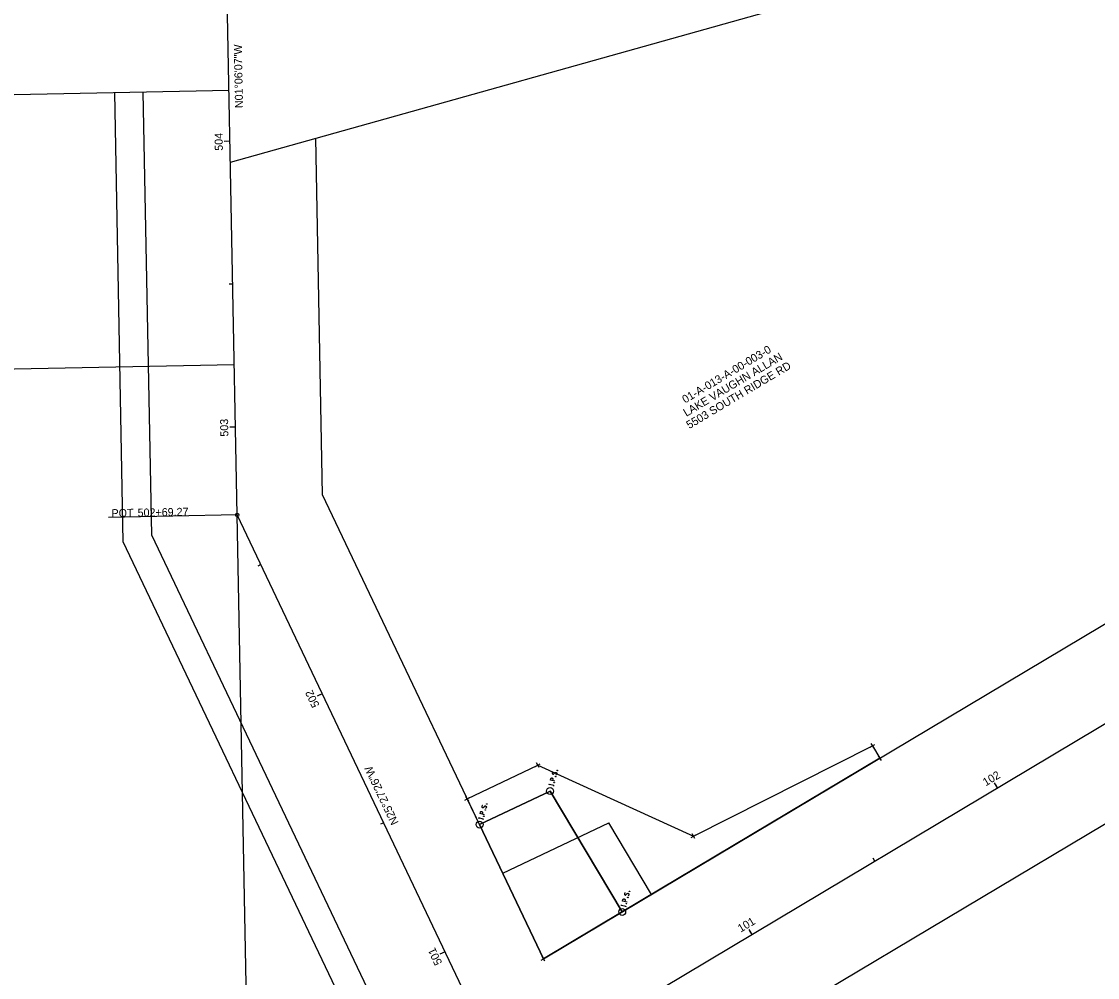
# Model space of a CAD drawing. Extents: x 2351593 to 2354159, y 766293 to 768001.
# Drawn here: x 2352246.2 to 2352622.6, y 766967.1 to 767301.5 of the extents above; entities that cross this region are included whole.
import ezdxf

# ---------------------------------------------------------------- set-up
doc = ezdxf.new("R2010")
doc.units = 0
for name, color, linetype in [('DV_X_Property_Line', 7, 'Continuous'), ('DV_X_Section_VMS_Line', 7, 'Continuous'), ('PTS_ANNO', 7, 'Continuous'), ('RW_P_Easement_Area', 7, 'Continuous'), ('RW_P_Esmt_SH', 7, 'Continuous'), ('RW_P_Esmt_TMP', 7, 'Continuous'), ('RW_P_Taking_Area', 7, 'Continuous'), ('RW_X_CL_100_Bearings', 7, 'Continuous'), ('RW_X_CL_100_Cardinal_Points', 7, 'Continuous'), ('RW_X_CL_500_Bearings', 7, 'Continuous'), ('RW_X_CL_500_Cardinal_Points', 7, 'Continuous'), ('RW_X_CL_500_Stations', 7, 'Continuous'), ('RW_X_Esmt_U', 7, 'Continuous'), ('SC_Scratch1', 7, 'Continuous'), ('SC_Scratch2', 7, 'Continuous'), ('SC_Scratch3', 7, 'Continuous'), ('SC_Scratch4', 7, 'Continuous'), ('SV_P_Control_Cells_Set', 7, 'Continuous'), ('SV_P_Mon_Cells_Set', 7, 'Continuous'), ('V-SURV-PARL-LINE', 7, 'Continuous'), ('V-SURV-RWAY-CNTR', 7, 'Continuous')]:
    doc.layers.add(name, color=color, linetype=linetype)

msp = doc.modelspace()

# ---------------------------------------------------------------- linework, layer by layer
at = {"layer": 'DV_X_Property_Line'}
for p, q in [((2352319.24, 767252.27), (2352591.72, 767328.7)), ((2352318.76, 767277.31), (2352107.01, 767273.24)), ((2352320.6, 767181.33), (2352109.81, 767177.28))]:
    msp.add_line(p, q, dxfattribs=at)
at = {"layer": 'DV_X_Section_VMS_Line'}
msp.add_line((2352337.69, 766292.88), (2352321.61, 767128.88), dxfattribs=at)
at = {"layer": 'PTS_ANNO'}
for p, q in [((2352428.78, 766973.55), (2354128.21, 767987.61)), ((2352450.22, 766916.47), (2354158.95, 767936.09)), ((2352291.74, 767121.83), (2352288.76, 767276.74)), ((2352351.48, 767135.93), (2352349.08, 767260.64)), ((2352428.78, 766973.55), (2352351.48, 767135.93)), ((2352377.03, 766942.67), (2352291.74, 767121.83))]:
    msp.add_line(p, q, dxfattribs=at)
at = {"layer": 'RW_P_Easement_Area'}
for p, q in [((2352481.24, 767016.49), (2352543.91, 767048.07)), ((2352543.91, 767048.07), (2352546.47, 767043.77)), ((2352546.47, 767043.77), (2352456.31, 766989.97)), ((2352402.11, 767029.58), (2352426.77, 767041.31)), ((2352426.77, 767041.31), (2352481.24, 767016.49)), ((2352431.06, 767032.28), (2352406.41, 767020.54)), ((2352456.31, 766989.97), (2352431.06, 767032.28)), ((2352406.41, 767020.54), (2352402.11, 767029.58))]:
    msp.add_line(p, q, dxfattribs=at)
at = {"layer": 'RW_P_Esmt_SH'}
for p, q in [((2352406.41, 767020.54), (2352431.06, 767032.28)), ((2352406.41, 767020.54), (2352431.06, 767032.28)), ((2352431.06, 767032.28), (2352456.31, 766989.97)), ((2352431.06, 767032.28), (2352456.31, 766989.97))]:
    msp.add_line(p, q, dxfattribs=at)
at = {"layer": 'RW_P_Esmt_TMP'}
for p, q in [((2352481.24, 767016.49), (2352543.91, 767048.07)), ((2352543.91, 767048.07), (2352546.47, 767043.77)), ((2352402.11, 767029.57), (2352426.76, 767041.31)), ((2352426.76, 767041.31), (2352481.24, 767016.49))]:
    msp.add_line(p, q, dxfattribs=at)
at = {"layer": 'RW_P_Taking_Area'}
for p, q in [((2352406.41, 767020.54), (2352431.06, 767032.28)), ((2352431.06, 767032.28), (2352456.31, 766989.97)), ((2352428.78, 766973.55), (2352406.41, 767020.54)), ((2352456.31, 766989.97), (2352428.78, 766973.55))]:
    msp.add_line(p, q, dxfattribs=at)
at = {"layer": 'RW_X_CL_100_Cardinal_Points'}
msp.add_line((2352321.61, 767128.88), (2352276.62, 767128.01), dxfattribs=at)
msp.add_circle((2352321.61, 767128.88), 0.6, dxfattribs=at)
at = {"layer": 'RW_X_CL_500_Cardinal_Points'}
msp.add_line((2352321.61, 767128.88), (2352276.62, 767128.01), dxfattribs=at)
msp.add_circle((2352321.61, 767128.88), 0.6, dxfattribs=at)
at = {"layer": 'RW_X_CL_500_Stations'}
for p, q in [((2352319.1, 767259.59), (2352317.9, 767259.56)), ((2352321.02, 767159.6), (2352319.82, 767159.58)), ((2352351.38, 767066.34), (2352350.3, 767065.82)), ((2352587.61, 767033.38), (2352586.99, 767034.41)), ((2352501.73, 766982.14), (2352501.12, 766983.17)), ((2352394.37, 766976.05), (2352393.28, 766975.53))]:
    msp.add_line(p, q, dxfattribs=at)
at = {"layer": 'RW_X_Esmt_U'}
for p, q in [((2352281.78, 767119.48), (2352278.76, 767276.54)), ((2352368.41, 766937.52), (2352281.78, 767119.48))]:
    msp.add_line(p, q, dxfattribs=at)
at = {"layer": 'SC_Scratch2'}
msp.add_lwpolyline([(2352431.06, 767032.28), (2352406.41, 767020.54), (2352428.78, 766973.55), (2352456.31, 766989.97)], close=True, dxfattribs=at)
at = {"layer": 'SC_Scratch3'}
msp.add_lwpolyline([(2352402.11, 767029.57), (2352426.76, 767041.31), (2352481.24, 767016.49), (2352543.91, 767048.07), (2352546.47, 767043.77), (2352456.31, 766989.97), (2352431.06, 767032.28), (2352406.41, 767020.54)], close=True, dxfattribs=at)
at = {"layer": 'SC_Scratch4'}
for p in [(2352414.52, 767003.5), (2352466.61, 766996.12)]:
    msp.add_line(p, (2352451.66, 767021.18), dxfattribs=at)
at = {"layer": 'SV_P_Control_Cells_Set'}
for p, q in [((2352543.1, 767047.58), (2352544.72, 767048.55)), ((2352544.39, 767047.26), (2352543.43, 767048.88)), ((2352545.66, 767043.29), (2352547.28, 767044.26)), ((2352546.96, 767042.96), (2352545.99, 767044.58)), ((2352425.96, 767040.82), (2352427.58, 767041.79)), ((2352427.25, 767040.5), (2352426.28, 767042.12)), ((2352401.3, 767029.09), (2352402.93, 767030.06)), ((2352402.6, 767028.77), (2352401.63, 767030.39)), ((2352481.72, 767015.68), (2352480.75, 767017.3)), ((2352480.43, 767016.01), (2352482.05, 767016.97)), ((2352427.97, 766973.06), (2352429.59, 766974.03)), ((2352429.27, 766972.74), (2352428.3, 766974.36))]:
    msp.add_line(p, q, dxfattribs=at)
at = {"layer": 'SV_P_Mon_Cells_Set'}
for points in [[(2352432.75, 767035.73), (2352431.2, 767036.12), (2352431.33, 767036.63), (2352431.36, 767036.68), (2352431.4, 767036.75), (2352431.43, 767036.78), (2352431.47, 767036.81), (2352431.54, 767036.83), (2352431.61, 767036.85), (2352431.71, 767036.85), (2352431.86, 767036.81), (2352431.9, 767036.79), (2352431.97, 767036.75), (2352432.05, 767036.68), (2352432.07, 767036.63), (2352432.09, 767036.59), (2352432.1, 767036.53), (2352432.09, 767036.44), (2352431.96, 767035.93)], [(2352432.05, 767039.01), (2352432.02, 767039), (2352431.99, 767038.97), (2352431.93, 767038.88), (2352431.87, 767038.77), (2352431.85, 767038.69), (2352431.84, 767038.65), (2352431.84, 767038.51), (2352431.89, 767038.37), (2352431.97, 767038.27), (2352432.06, 767038.22), (2352432.13, 767038.21), (2352432.23, 767038.2), (2352432.34, 767038.27), (2352432.86, 767038.76), (2352432.92, 767038.8), (2352432.97, 767038.81), (2352433.05, 767038.81), (2352433.13, 767038.8), (2352433.2, 767038.77), (2352433.24, 767038.74), (2352433.3, 767038.71), (2352433.34, 767038.67), (2352433.37, 767038.64), (2352433.4, 767038.6), (2352433.42, 767038.56), (2352433.43, 767038.51), (2352433.43, 767038.48), (2352433.42, 767038.38), (2352433.38, 767038.23), (2352433.34, 767038.14), (2352433.22, 767038.02), (2352433.12, 767037.96)], [(2352432.95, 767037.37), (2352432.96, 767037.43), (2352432.99, 767037.45), (2352433.05, 767037.47), (2352433.11, 767037.46), (2352433.15, 767037.41), (2352433.17, 767037.38), (2352433.16, 767037.32), (2352433.12, 767037.3), (2352433.07, 767037.28), (2352433, 767037.29), (2352432.96, 767037.34), (2352432.95, 767037.37)], [(2352433.48, 767039.49), (2352433.5, 767039.54), (2352433.53, 767039.57), (2352433.59, 767039.59), (2352433.65, 767039.57), (2352433.69, 767039.53), (2352433.7, 767039.49), (2352433.69, 767039.44), (2352433.66, 767039.41), (2352433.6, 767039.39), (2352433.54, 767039.41), (2352433.5, 767039.45), (2352433.48, 767039.49)], [(2352430.78, 767034.43), (2352430.86, 767034.77)], [(2352432.37, 767034.21), (2352430.82, 767034.6)], [(2352432.33, 767034.04), (2352432.41, 767034.38)], [(2352432.4, 767035.19), (2352432.41, 767035.25), (2352432.44, 767035.27), (2352432.5, 767035.29), (2352432.56, 767035.28), (2352432.6, 767035.23), (2352432.62, 767035.2), (2352432.6, 767035.14), (2352432.57, 767035.12), (2352432.52, 767035.1), (2352432.45, 767035.11), (2352432.41, 767035.16), (2352432.4, 767035.19)], [(2352408.11, 767023.99), (2352406.56, 767024.38), (2352406.68, 767024.9), (2352406.71, 767024.95), (2352406.75, 767025.02), (2352406.79, 767025.04), (2352406.82, 767025.07), (2352406.89, 767025.09), (2352406.96, 767025.11), (2352407.06, 767025.11), (2352407.21, 767025.07), (2352407.26, 767025.05), (2352407.32, 767025.01), (2352407.4, 767024.94), (2352407.42, 767024.89), (2352407.44, 767024.85), (2352407.45, 767024.79), (2352407.44, 767024.71), (2352407.31, 767024.19)], [(2352407.4, 767027.27), (2352407.37, 767027.26), (2352407.34, 767027.23), (2352407.28, 767027.15), (2352407.22, 767027.03), (2352407.2, 767026.95), (2352407.19, 767026.92), (2352407.2, 767026.77), (2352407.24, 767026.63), (2352407.32, 767026.53), (2352407.41, 767026.49), (2352407.48, 767026.47), (2352407.59, 767026.47), (2352407.69, 767026.53), (2352408.21, 767027.02), (2352408.27, 767027.07), (2352408.33, 767027.07), (2352408.4, 767027.08), (2352408.48, 767027.06), (2352408.55, 767027.03), (2352408.59, 767027.01), (2352408.65, 767026.97), (2352408.69, 767026.94), (2352408.73, 767026.91), (2352408.75, 767026.86), (2352408.77, 767026.83), (2352408.78, 767026.78), (2352408.79, 767026.74), (2352408.78, 767026.64), (2352408.74, 767026.49), (2352408.69, 767026.4), (2352408.57, 767026.29), (2352408.47, 767026.22)], [(2352408.3, 767025.64), (2352408.31, 767025.69), (2352408.35, 767025.72), (2352408.4, 767025.74), (2352408.47, 767025.72), (2352408.51, 767025.68), (2352408.52, 767025.64), (2352408.51, 767025.58), (2352408.48, 767025.56), (2352408.42, 767025.54), (2352408.36, 767025.55), (2352408.32, 767025.6), (2352408.3, 767025.64)], [(2352408.84, 767027.75), (2352408.85, 767027.81), (2352408.88, 767027.83), (2352408.94, 767027.85), (2352409, 767027.84), (2352409.04, 767027.79), (2352409.06, 767027.75), (2352409.04, 767027.7), (2352409.01, 767027.67), (2352408.95, 767027.66), (2352408.89, 767027.67), (2352408.85, 767027.71), (2352408.84, 767027.75)], [(2352406.13, 767022.7), (2352406.22, 767023.04)], [(2352407.72, 767022.47), (2352406.17, 767022.87)], [(2352407.68, 767022.3), (2352407.77, 767022.65)], [(2352407.75, 767023.46), (2352407.76, 767023.51), (2352407.8, 767023.54), (2352407.85, 767023.56), (2352407.91, 767023.54), (2352407.96, 767023.5), (2352407.97, 767023.46), (2352407.96, 767023.4), (2352407.93, 767023.38), (2352407.87, 767023.36), (2352407.81, 767023.37), (2352407.77, 767023.42), (2352407.75, 767023.46)], [(2352458, 766993.42), (2352456.45, 766993.81), (2352456.58, 766994.32), (2352456.6, 766994.37), (2352456.65, 766994.44), (2352456.68, 766994.47), (2352456.71, 766994.5), (2352456.78, 766994.52), (2352456.85, 766994.54), (2352456.96, 766994.54), (2352457.1, 766994.5), (2352457.15, 766994.48), (2352457.22, 766994.44), (2352457.29, 766994.37), (2352457.32, 766994.32), (2352457.33, 766994.28), (2352457.35, 766994.22), (2352457.34, 766994.13), (2352457.21, 766993.62)], [(2352457.3, 766996.7), (2352457.27, 766996.69), (2352457.23, 766996.66), (2352457.17, 766996.57), (2352457.12, 766996.46), (2352457.1, 766996.38), (2352457.09, 766996.34), (2352457.09, 766996.2), (2352457.13, 766996.06), (2352457.21, 766995.96), (2352457.3, 766995.91), (2352457.38, 766995.9), (2352457.48, 766995.89), (2352457.59, 766995.96), (2352458.1, 766996.45), (2352458.17, 766996.49), (2352458.22, 766996.5), (2352458.3, 766996.51), (2352458.37, 766996.49), (2352458.44, 766996.46), (2352458.49, 766996.43), (2352458.54, 766996.4), (2352458.59, 766996.36), (2352458.62, 766996.33), (2352458.65, 766996.29), (2352458.66, 766996.25), (2352458.68, 766996.2), (2352458.68, 766996.17), (2352458.67, 766996.07), (2352458.63, 766995.92), (2352458.58, 766995.83), (2352458.46, 766995.71), (2352458.37, 766995.65)], [(2352458.19, 766995.06), (2352458.21, 766995.12), (2352458.24, 766995.14), (2352458.3, 766995.16), (2352458.36, 766995.15), (2352458.4, 766995.1), (2352458.42, 766995.07), (2352458.4, 766995.01), (2352458.37, 766994.99), (2352458.31, 766994.97), (2352458.25, 766994.98), (2352458.21, 766995.03), (2352458.19, 766995.06)], [(2352458.73, 766997.18), (2352458.74, 766997.23), (2352458.78, 766997.26), (2352458.83, 766997.28), (2352458.89, 766997.26), (2352458.93, 766997.22), (2352458.95, 766997.18), (2352458.94, 766997.13), (2352458.9, 766997.1), (2352458.85, 766997.08), (2352458.79, 766997.1), (2352458.75, 766997.14), (2352458.73, 766997.18)], [(2352456.02, 766992.12), (2352456.11, 766992.46)], [(2352457.62, 766991.9), (2352456.07, 766992.29)], [(2352457.57, 766991.73), (2352457.66, 766992.07)], [(2352457.64, 766992.88), (2352457.66, 766992.94), (2352457.69, 766992.96), (2352457.75, 766992.98), (2352457.81, 766992.97), (2352457.85, 766992.92), (2352457.87, 766992.89), (2352457.85, 766992.83), (2352457.82, 766992.81), (2352457.76, 766992.79), (2352457.7, 766992.8), (2352457.66, 766992.85), (2352457.64, 766992.88)]]:
    msp.add_lwpolyline(points, dxfattribs=at)
for centre in [(2352431.06, 767032.28), (2352406.41, 767020.54), (2352456.31, 766989.97)]:
    msp.add_circle(centre, 1.2, dxfattribs=at)
at = {"layer": 'V-SURV-PARL-LINE'}
for p, q in [((2352319.1, 767259.59), (2352317.1, 767259.55)), ((2352320.06, 767209.6), (2352318.86, 767209.57)), ((2352321.02, 767159.6), (2352319.02, 767159.57)), ((2352329.89, 767111.48), (2352328.81, 767110.97)), ((2352351.38, 767066.34), (2352349.58, 767065.48)), ((2352587.61, 767033.38), (2352586.58, 767035.1)), ((2352372.88, 767021.19), (2352371.79, 767020.67)), ((2352544.67, 767007.76), (2352544.06, 767008.79)), ((2352501.73, 766982.14), (2352500.71, 766983.86)), ((2352394.37, 766976.05), (2352392.56, 766975.19))]:
    msp.add_line(p, q, dxfattribs=at)
at = {"layer": 'V-SURV-RWAY-CNTR'}
for p, q in [((2351616.47, 766453.89), (2354143.58, 767961.85)), ((2352321.61, 767128.88), (2352315.68, 767437.12)), ((2352415.86, 766930.9), (2352321.61, 767128.88))]:
    msp.add_line(p, q, dxfattribs=at)

# ---------------------------------------------------------------- texts
at = {"layer": 'RW_X_CL_100_Bearings'}
for s, rotation, p in [('N01°06\'07"W', 91.1019, (2352323.67, 767271.23)), ('N25°27\'26"W', 115.4572, (2352378.17, 767021.24))]:
    msp.add_text(s, height=2.8, rotation=rotation, dxfattribs=at).set_placement(p)
at = {"layer": 'RW_X_CL_100_Cardinal_Points'}
for s, p in [('POT', (2352277.68, 767128.08)), ('502+69.27', (2352286.81, 767128.26))]:
    msp.add_text(s, height=2.8, rotation=1.1019, dxfattribs=at).set_placement(p)
at = {"layer": 'RW_X_CL_500_Bearings'}
for s, rotation, p in [('N01°06\'07"W', 91.1019, (2352323.67, 767271.23)), ('N25°27\'26"W', 115.4572, (2352378.17, 767021.24))]:
    msp.add_text(s, height=2.8, rotation=rotation, dxfattribs=at).set_placement(p)
at = {"layer": 'RW_X_CL_500_Cardinal_Points'}
for s, p in [('POT', (2352277.68, 767128.08)), ('502+69.27', (2352286.81, 767128.26))]:
    msp.add_text(s, height=2.8, rotation=1.1019, dxfattribs=at).set_placement(p)
at = {"layer": 'SC_Scratch1'}
for s, p in [('01-A-013-A-00-003-0', (2352478.33, 767167.82)), ('LAKE VAUGHN ALLAN', (2352478.73, 767163.16)), ('5503 SOUTH RIDGE RD', (2352479.77, 767158.89))]:
    msp.add_text(s, height=2.8, rotation=30.825, dxfattribs=at).set_placement(p)
at = {"layer": 'V-SURV-PARL-LINE'}
for s, rotation, p in [('504', 91.1019, (2352316.61, 767256.3)), ('503', 91.1019, (2352318.54, 767156.29)), ('502', 115.4572, (2352350.49, 767062.29)), ('102', 30.825, (2352583.49, 767033.89)), ('101', 30.825, (2352497.76, 766982.73)), ('501', 115.4572, (2352393.41, 766972.14))]:
    msp.add_text(s, height=2.8, rotation=rotation, dxfattribs=at).set_placement(p)

doc.saveas('drawing.dxf')
